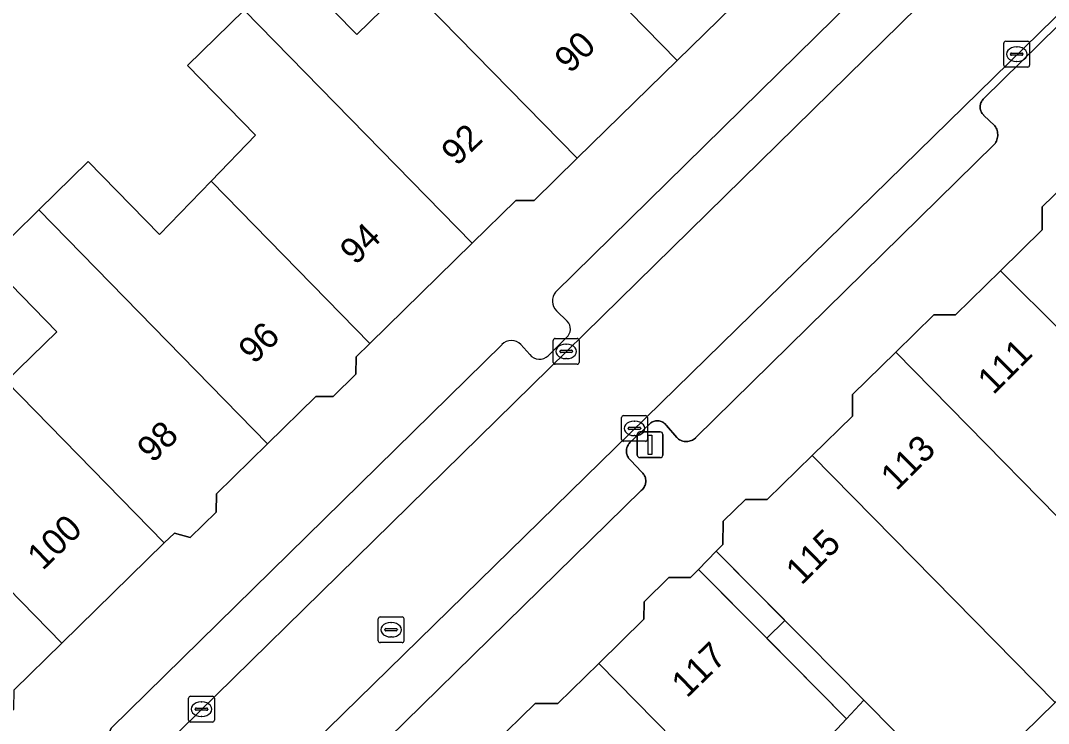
# Model space of a CAD drawing. Extents: x 160856 to 161310, y 384024 to 384878.
# Drawn here: x 161043.45 to 161083.27, y 384645.25 to 384672.48 of the extents above; entities that cross this region are included whole.
import ezdxf

# ---------------------------------------------------------------- set-up
doc = ezdxf.new("R2010")
doc.units = 0
for name, color, linetype in [('IMGEO_Erf', 7, 'Continuous'), ('IMGEO_Kolk', 7, 'Continuous'), ('IMGEO_Lichtmast', 7, 'Continuous'), ('IMGEO_Pand', 7, 'Continuous'), ('IMGEO_Pand_nummerreeks', 7, 'Continuous'), ('IMGEO_Pand_overbouw', 7, 'Continuous'), ('IMGEO_Parkeervlak_open', 7, 'Continuous'), ('IMGEO_Rijbaan_lokaal_gesloten', 7, 'Continuous'), ('IMGEO_Rioolput', 7, 'Continuous'), ('IMGEO_Voetpad_open', 7, 'Continuous')]:
    doc.layers.add(name, color=color, linetype=linetype)

msp = doc.modelspace()

# ---------------------------------------------------------------- linework, layer by layer
at = {"layer": 'IMGEO_Erf'}
for points in [[(161053.863, 384674.603), (161056.476, 384671.933), (161058.443, 384673.858)], [(161042.888, 384658.505), (161044.847, 384660.422), (161042.148, 384663.181), (161044.154, 384665.144), (161046.067, 384667.016), (161048.834, 384664.187), (161050.828, 384666.256), (161052.547, 384668.039), (161049.91, 384670.735), (161052.106, 384672.884)], [(161083.528, 384646.059), (161079.815, 384642.413), (161076.117, 384646.148), (161075.44, 384645.431), (161073.602, 384643.447)]]:
    msp.add_lwpolyline(points, dxfattribs=at)
msp.add_lwpolyline([(161069.712, 384651.21), (161073.232, 384647.659), (161075.44, 384645.431), (161076.117, 384646.148), (161073.917, 384648.37), (161070.398, 384651.922)], close=True, dxfattribs=at)
at = {"layer": 'IMGEO_Kolk'}
for p, q in [((161081.539, 384670.751), (161081.539, 384671.603)), ((161081.614, 384671.677), (161082.466, 384671.677)), ((161082.027, 384671.457), (161082.052, 384671.457)), ((161082.54, 384671.603), (161082.54, 384670.751)), ((161081.798, 384671.171), (161081.798, 384671.183)), ((161082.236, 384671.134), (161081.838, 384671.134)), ((161081.841, 384671.22), (161082.239, 384671.22)), ((161082.282, 384671.183), (161082.282, 384671.171)), ((161082.466, 384670.677), (161081.614, 384670.677)), ((161082.05, 384670.897), (161082.025, 384670.897)), ((161064.086, 384659.235), (161064.086, 384660.087)), ((161064.161, 384660.161), (161065.013, 384660.161)), ((161064.574, 384659.941), (161064.599, 384659.941)), ((161065.087, 384660.087), (161065.087, 384659.235)), ((161064.345, 384659.655), (161064.345, 384659.667)), ((161064.783, 384659.618), (161064.385, 384659.618)), ((161064.388, 384659.704), (161064.786, 384659.704)), ((161064.829, 384659.667), (161064.829, 384659.655)), ((161065.013, 384659.161), (161064.161, 384659.161)), ((161064.597, 384659.381), (161064.572, 384659.381)), ((161066.729, 384656.251), (161066.729, 384657.103)), ((161066.804, 384657.177), (161067.656, 384657.177)), ((161067.73, 384657.103), (161067.73, 384656.251)), ((161067.031, 384656.72), (161067.429, 384656.72)), ((161067.217, 384656.957), (161067.242, 384656.957)), ((161066.988, 384656.671), (161066.988, 384656.683)), ((161067.426, 384656.634), (161067.028, 384656.634)), ((161067.24, 384656.397), (161067.215, 384656.397)), ((161067.472, 384656.683), (161067.472, 384656.671)), ((161067.656, 384656.177), (161066.804, 384656.177)), ((161049.955, 384645.374), (161049.955, 384646.226)), ((161050.03, 384646.3), (161050.882, 384646.3)), ((161050.443, 384646.08), (161050.468, 384646.08)), ((161050.956, 384646.226), (161050.956, 384645.374)), ((161050.214, 384645.794), (161050.214, 384645.806)), ((161050.652, 384645.757), (161050.254, 384645.757)), ((161050.257, 384645.843), (161050.655, 384645.843)), ((161050.698, 384645.806), (161050.698, 384645.794)), ((161050.882, 384645.3), (161050.03, 384645.3)), ((161050.466, 384645.52), (161050.441, 384645.52))]:
    msp.add_line(p, q, dxfattribs=at)
for points in [[(161081.539, 384670.751), (161081.539, 384671.603)], [(161081.614, 384671.677), (161082.466, 384671.677)], [(161082.54, 384671.603), (161082.54, 384670.751)], [(161082.466, 384670.677), (161081.614, 384670.677)], [(161064.086, 384659.235), (161064.086, 384660.087)], [(161064.161, 384660.161), (161065.013, 384660.161)], [(161065.087, 384660.087), (161065.087, 384659.235)], [(161065.013, 384659.161), (161064.161, 384659.161)], [(161066.729, 384656.251), (161066.729, 384657.103)], [(161066.804, 384657.177), (161067.656, 384657.177)], [(161067.73, 384657.103), (161067.73, 384656.251)], [(161067.656, 384656.177), (161066.804, 384656.177)], [(161049.955, 384645.374), (161049.955, 384646.226)], [(161050.03, 384646.3), (161050.882, 384646.3)], [(161050.956, 384646.226), (161050.956, 384645.374)], [(161050.882, 384645.3), (161050.03, 384645.3)]]:
    msp.add_lwpolyline(points, dxfattribs=at)
for centre, radius, start, end in [((161081.616, 384671.601), 0.0765, 91.552, 178.448), ((161081.616, 384671.601), 0.0765, 91.552, 178.448), ((161082.464, 384671.601), 0.0765, 1.552, 88.448), ((161082.464, 384671.601), 0.0765, 1.552, 88.448), ((161081.838, 384671.18), 0.0403, 85.8775, 175.7526), ((161081.835, 384671.17), 0.0366, 178.938, 274.7102), ((161082.239, 384671.177), 0.043, 264.8664, 352.4533), ((161082.243, 384671.182), 0.0386, 1.7309, 96.639), ((161081.616, 384670.753), 0.0765, 181.552, 268.448), ((161081.616, 384670.753), 0.0765, 181.552, 268.448), ((161082.464, 384670.753), 0.0765, 271.552, 358.448), ((161082.464, 384670.753), 0.0765, 271.552, 358.448), ((161064.163, 384660.085), 0.0765, 91.552, 178.448), ((161064.163, 384660.085), 0.0765, 91.552, 178.448), ((161065.011, 384660.085), 0.0765, 1.552, 88.448), ((161065.011, 384660.085), 0.0765, 1.552, 88.448), ((161064.385, 384659.664), 0.0403, 85.8775, 175.7526), ((161064.382, 384659.654), 0.0366, 178.938, 274.7102), ((161064.786, 384659.661), 0.043, 264.8664, 352.4533), ((161064.79, 384659.666), 0.0386, 1.7309, 96.639), ((161064.163, 384659.237), 0.0765, 181.552, 268.448), ((161064.163, 384659.237), 0.0765, 181.552, 268.448), ((161065.011, 384659.237), 0.0765, 271.552, 358.448), ((161065.011, 384659.237), 0.0765, 271.552, 358.448), ((161066.806, 384657.101), 0.0765, 91.552, 178.448), ((161066.806, 384657.101), 0.0765, 91.552, 178.448), ((161067.654, 384657.101), 0.0765, 1.552, 88.448), ((161067.654, 384657.101), 0.0765, 1.552, 88.448), ((161067.028, 384656.68), 0.0403, 85.8775, 175.7526), ((161067.433, 384656.682), 0.0386, 1.7309, 96.639), ((161067.025, 384656.67), 0.0366, 178.938, 274.7102), ((161067.429, 384656.677), 0.043, 264.8664, 352.4533), ((161066.806, 384656.253), 0.0765, 181.552, 268.448), ((161066.806, 384656.253), 0.0765, 181.552, 268.448), ((161067.654, 384656.253), 0.0765, 271.552, 358.448), ((161067.654, 384656.253), 0.0765, 271.552, 358.448), ((161050.032, 384646.224), 0.0765, 91.552, 178.448), ((161050.032, 384646.224), 0.0765, 91.552, 178.448), ((161050.88, 384646.224), 0.0765, 1.552, 88.448), ((161050.88, 384646.224), 0.0765, 1.552, 88.448), ((161050.254, 384645.803), 0.0403, 85.8775, 175.7526), ((161050.251, 384645.793), 0.0366, 178.938, 274.7102), ((161050.655, 384645.8), 0.043, 264.8664, 352.4533), ((161050.659, 384645.805), 0.0386, 1.7309, 96.639), ((161050.032, 384645.376), 0.0765, 181.552, 268.448), ((161050.032, 384645.376), 0.0765, 181.552, 268.448), ((161050.88, 384645.376), 0.0765, 271.552, 358.448), ((161050.88, 384645.376), 0.0765, 271.552, 358.448)]:
    msp.add_arc(centre, radius, start, end, dxfattribs=at)
for centre, major_axis, ratio, start_param, end_param in [((161082.026, 384671.177), (-0.387, 0.002), 0.722429, 4.712389, 7.853982), ((161082.051, 384671.177), (-0.39, 0.002), 0.717154, 1.570796, 4.712389), ((161064.573, 384659.661), (-0.387, 0.002), 0.722429, 4.712389, 7.853982), ((161064.598, 384659.661), (-0.39, 0.002), 0.717154, 1.570796, 4.712389), ((161067.216, 384656.677), (-0.387, 0.002), 0.722429, 4.712389, 7.853982), ((161067.241, 384656.677), (-0.39, 0.002), 0.717154, 1.570796, 4.712389), ((161050.442, 384645.8), (-0.387, 0.002), 0.722429, 4.712389, 7.853982), ((161050.467, 384645.8), (-0.39, 0.002), 0.717154, 1.570796, 4.712389)]:
    msp.add_ellipse(centre, major_axis=major_axis, ratio=ratio, start_param=start_param, end_param=end_param, dxfattribs=at)
at = {"layer": 'IMGEO_Lichtmast'}
for p, q in [((161067.339, 384655.646), (161067.339, 384656.446)), ((161067.339, 384656.446), (161067.339, 384655.646)), ((161067.439, 384656.546), (161068.229, 384656.546)), ((161068.229, 384656.546), (161067.439, 384656.546)), ((161068.329, 384656.446), (161068.329, 384655.646)), ((161068.329, 384655.646), (161068.329, 384656.446)), ((161068.229, 384655.546), (161067.439, 384655.546)), ((161067.439, 384655.546), (161068.229, 384655.546))]:
    msp.add_line(p, q, dxfattribs=at)
msp.add_lwpolyline([(161067.759, 384656.421), (161067.909, 384656.421), (161067.909, 384655.671), (161067.759, 384655.671), (161067.759, 384656.421)], dxfattribs=at)
for centre, start, end in [((161067.439, 384656.446), 90, 180), ((161067.439, 384656.446), 90, 180), ((161068.229, 384656.446), 0, 90), ((161068.229, 384656.446), 360, 90), ((161067.439, 384655.646), 180, 270), ((161067.439, 384655.646), 180, 270), ((161068.229, 384655.646), 270, 0), ((161068.229, 384655.646), 270, 0)]:
    msp.add_arc(centre, 0.1, start, end, dxfattribs=at)
at = {"layer": 'IMGEO_Pand'}
for points in [[(161066.889, 384681.575), (161064.573, 384679.31), (161061.029, 384682.932), (161060.87, 384682.777), (161059.041, 384680.994), (161068.886, 384670.932), (161073.184, 384675.14)], [(161059.041, 384680.994), (161056.988, 384678.993), (161057.966, 384677.993), (161058.14, 384677.815), (161060.501, 384675.402), (161059.015, 384673.948), (161058.78, 384674.188), (161058.443, 384673.858), (161065.015, 384667.142), (161068.886, 384670.932)], [(161052.106, 384672.884), (161060.941, 384663.854), (161062.633, 384665.51), (161063.339, 384665.502), (161065.015, 384667.142), (161058.443, 384673.858), (161056.476, 384671.933), (161053.863, 384674.603)], [(161052.106, 384672.884), (161049.91, 384670.735), (161052.547, 384668.039), (161050.828, 384666.256), (161056.976, 384659.973), (161060.941, 384663.854)], [(161053.017, 384656.086), (161054.888, 384657.917), (161055.553, 384657.91), (161056.437, 384658.775), (161056.444, 384659.452), (161056.976, 384659.973), (161050.828, 384666.256), (161048.834, 384664.187), (161046.067, 384667.016), (161044.154, 384665.144)], [(161081.413, 384662.783), (161091.066, 384653.171), (161092.786, 384654.859), (161088.969, 384658.818), (161090.858, 384660.647), (161088.603, 384662.951), (161085.106, 384666.524), (161084.662, 384666.101), (161083.9, 384666.108), (161083.032, 384665.256), (161083.024, 384664.365)], [(161042.888, 384658.505), (161040.875, 384656.536), (161038.16, 384659.312), (161037.93, 384659.087), (161034.44, 384662.655), (161035.691, 384663.879), (161033.998, 384665.608), (161033.779, 384665.832), (161030.805, 384662.922), (161032.749, 384660.935), (161036.163, 384657.446), (161045.05, 384648.363), (161049.014, 384652.243)], [(161042.888, 384658.505), (161049.014, 384652.243), (161049.404, 384652.625), (161050.019, 384652.453), (161051.025, 384653.438), (161051.032, 384654.143), (161053.017, 384656.086), (161044.154, 384665.144), (161042.148, 384663.181), (161044.847, 384660.422)], [(161081.413, 384662.783), (161079.67, 384661.072), (161078.831, 384661.079), (161077.352, 384659.628), (161086.407, 384650.417), (161088.242, 384652.221), (161090.2, 384650.207), (161092.135, 384652.106), (161091.066, 384653.171)], [(161074.12, 384655.63), (161083.528, 384646.059), (161085.285, 384647.785), (161084.521, 384648.564), (161086.407, 384650.417), (161077.352, 384659.628), (161075.683, 384657.989), (161075.675, 384657.157)], [(161036.163, 384657.446), (161035.583, 384656.879), (161034.191, 384655.517), (161032.2, 384653.569), (161032.68, 384653.079), (161032.814, 384652.942), (161041.458, 384644.107), (161043.184, 384645.796), (161043.192, 384646.544), (161045.05, 384648.363)], [(161074.12, 384655.63), (161072.375, 384653.917), (161071.527, 384653.925), (161070.668, 384653.081), (161070.66, 384652.18), (161070.398, 384651.922), (161073.917, 384648.37), (161076.117, 384646.148), (161079.815, 384642.413), (161083.528, 384646.059)], [(161073.232, 384647.659), (161069.712, 384651.21), (161069.403, 384650.896), (161068.562, 384650.904), (161067.6, 384649.959), (161067.594, 384649.283), (161065.854, 384647.575), (161075.279, 384637.98), (161077.157, 384639.826), (161073.602, 384643.447), (161075.44, 384645.431)], [(161065.854, 384647.575), (161064.267, 384646.017), (161063.379, 384646.026), (161061.742, 384644.419), (161068.073, 384637.979), (161069.834, 384639.708), (161073.371, 384636.105), (161074.297, 384637.015), (161075.279, 384637.98)]]:
    msp.add_lwpolyline(points, close=True, dxfattribs=at)
at = {"layer": 'IMGEO_Pand_overbouw'}
for points in [[(161072.352, 384648.547), (161073.053, 384649.242), (161070.398, 384651.922), (161069.712, 384651.21)], [(161073.917, 384648.37), (161073.053, 384649.242), (161072.352, 384648.547), (161075.44, 384645.431), (161076.117, 384646.148)]]:
    msp.add_lwpolyline(points, close=True, dxfattribs=at)
at = {"layer": 'IMGEO_Parkeervlak_open'}
for points in [[(161045.943, 384641.353), (161047.62, 384642.996), (161093.847, 384688.359), (161094.179, 384688.665), (161098.356, 384692.696)], [(161096.984, 384685.767), (161048.906, 384638.739)], [(161075.693, 384673.266), (161064.172, 384661.961)], [(161052.469, 384639.551), (161067.493, 384654.272), (161067.525, 384654.299), (161067.554, 384654.33), (161067.58, 384654.362), (161067.603, 384654.397), (161067.623, 384654.434), (161067.64, 384654.473), (161067.653, 384654.512), (161067.662, 384654.553), (161067.668, 384654.595), (161067.67, 384654.636), (161067.668, 384654.678), (161067.663, 384654.72), (161067.654, 384654.761), (161067.641, 384654.801), (161067.625, 384654.839), (161067.605, 384654.876), (161067.583, 384654.911), (161067.557, 384654.944), (161067.528, 384654.975), (161067.507, 384654.994), (161067.089, 384655.439), (161067.058, 384655.466), (161067.029, 384655.496), (161067.004, 384655.528), (161066.981, 384655.563), (161066.962, 384655.599), (161066.946, 384655.636), (161066.933, 384655.675), (161066.924, 384655.715), (161066.918, 384655.756), (161066.916, 384655.797), (161066.918, 384655.838), (161066.924, 384655.879), (161066.933, 384655.919), (161066.945, 384655.958), (161066.961, 384655.996), (161066.981, 384656.032), (161067.003, 384656.066), (161067.029, 384656.098), (161067.057, 384656.128), (161067.787, 384656.813), (161067.839, 384656.868), (161067.868, 384656.892), (161067.899, 384656.913), (161067.933, 384656.932), (161067.967, 384656.947), (161068.003, 384656.959), (161068.04, 384656.968), (161068.077, 384656.973), (161068.115, 384656.975), (161068.153, 384656.974), (161068.191, 384656.969), (161068.228, 384656.961), (161068.264, 384656.95), (161068.299, 384656.936), (161068.332, 384656.918), (161068.364, 384656.898), (161068.394, 384656.874), (161068.422, 384656.849), (161068.447, 384656.82), (161068.47, 384656.79), (161068.866, 384656.326), (161068.901, 384656.294), (161068.938, 384656.265), (161068.978, 384656.24), (161069.02, 384656.218), (161069.064, 384656.2), (161069.109, 384656.186), (161069.155, 384656.176), (161069.202, 384656.17), (161069.249, 384656.169), (161069.297, 384656.172), (161069.343, 384656.179), (161069.389, 384656.19), (161069.434, 384656.205), (161069.477, 384656.224), (161069.519, 384656.247), (161069.558, 384656.274), (161069.594, 384656.304), (161069.612, 384656.32), (161081.171, 384667.678), (161081.202, 384667.72), (161081.23, 384667.764), (161081.253, 384667.81), (161081.273, 384667.858), (161081.288, 384667.908), (161081.298, 384667.959), (161081.304, 384668.011), (161081.305, 384668.063), (161081.301, 384668.115), (161081.293, 384668.166), (161081.28, 384668.217), (161081.263, 384668.266), (161081.242, 384668.313), (161081.216, 384668.359), (161081.187, 384668.402), (161081.176, 384668.415), (161080.769, 384668.806), (161080.752, 384668.822), (161080.726, 384668.851), (161080.702, 384668.882), (161080.68, 384668.915), (161080.662, 384668.951), (161080.647, 384668.987), (161080.636, 384669.025), (161080.628, 384669.064), (161080.623, 384669.103), (161080.622, 384669.143), (161080.624, 384669.182), (161080.63, 384669.221), (161080.64, 384669.26), (161080.653, 384669.297), (161080.669, 384669.333), (161080.688, 384669.368), (161080.71, 384669.4), (161080.735, 384669.431), (161080.763, 384669.459), (161083.642, 384672.284)], [(161064.208, 384661.229), (161064.625, 384660.828)], [(161062.098, 384659.927), (161046.962, 384645.066), (161046.654, 384644.358), (161046.58, 384642.692)], [(161063.175, 384659.539), (161062.823, 384659.924)], [(161064.593, 384660.198), (161063.883, 384659.493)]]:
    msp.add_lwpolyline(points, dxfattribs=at)
for centre, radius, start, end in [((161064.606, 384661.615), 0.555, 141.4949, 224.1363), ((161064.322, 384660.528), 0.427, 309.4723, 44.7122), ((161062.459, 384659.599), 0.488, 41.7355, 137.7903), ((161063.55, 384659.84), 0.481, 218.7209, 313.8443)]:
    msp.add_arc(centre, radius, start, end, dxfattribs=at)
at = {"layer": 'IMGEO_Rijbaan_lokaal_gesloten'}
msp.add_lwpolyline([(161045.97, 384635.823), (161048.906, 384638.739), (161096.984, 384685.767), (161094.179, 384688.665), (161093.847, 384688.359), (161047.62, 384642.996), (161045.943, 384641.353), (161041.622, 384637.072), (161035.757, 384631.338), (161021.935, 384619.355), (161000, 384600.273), (160978.384, 384581.429), (160977.321, 384580.465), (160976.957, 384580.135), (160976.745, 384579.943)], dxfattribs=at)
at = {"layer": 'IMGEO_Rioolput'}
for p, q in [((161057.3, 384648.451), (161057.3, 384649.303)), ((161057.375, 384649.377), (161058.227, 384649.377)), ((161057.788, 384649.157), (161057.813, 384649.157)), ((161058.301, 384649.303), (161058.301, 384648.451)), ((161057.559, 384648.871), (161057.559, 384648.883)), ((161057.997, 384648.834), (161057.599, 384648.834)), ((161057.602, 384648.92), (161058, 384648.92)), ((161058.043, 384648.883), (161058.043, 384648.871)), ((161058.227, 384648.377), (161057.375, 384648.377)), ((161057.811, 384648.597), (161057.786, 384648.597))]:
    msp.add_line(p, q, dxfattribs=at)
for points in [[(161057.3, 384648.451), (161057.3, 384649.303)], [(161057.375, 384649.377), (161058.227, 384649.377)], [(161058.301, 384649.303), (161058.301, 384648.451)], [(161058.227, 384648.377), (161057.375, 384648.377)]]:
    msp.add_lwpolyline(points, dxfattribs=at)
for centre, radius, start, end in [((161057.377, 384649.301), 0.0765, 91.552, 178.448), ((161057.377, 384649.301), 0.0765, 91.552, 178.448), ((161058.225, 384649.301), 0.0765, 1.552, 88.448), ((161058.225, 384649.301), 0.0765, 1.552, 88.448), ((161057.599, 384648.88), 0.0403, 85.8775, 175.7526), ((161057.596, 384648.87), 0.0366, 178.938, 274.7102), ((161058, 384648.877), 0.043, 264.8664, 352.4533), ((161058.004, 384648.882), 0.0386, 1.7309, 96.639), ((161057.377, 384648.453), 0.0765, 181.552, 268.448), ((161057.377, 384648.453), 0.0765, 181.552, 268.448), ((161058.225, 384648.453), 0.0765, 271.552, 358.448), ((161058.225, 384648.453), 0.0765, 271.552, 358.448)]:
    msp.add_arc(centre, radius, start, end, dxfattribs=at)
for centre, major_axis, ratio, start_param, end_param in [((161057.787, 384648.877), (-0.387, 0.002), 0.722429, 4.712389, 7.853982), ((161057.812, 384648.877), (-0.39, 0.002), 0.717154, 1.570796, 4.712389)]:
    msp.add_ellipse(centre, major_axis=major_axis, ratio=ratio, start_param=start_param, end_param=end_param, dxfattribs=at)
at = {"layer": 'IMGEO_Voetpad_open'}
for points in [[(161089.608, 384691.356), (161082.942, 384684.859), (161081.588, 384683.366), (161077.149, 384679.021), (161073.184, 384675.14), (161068.886, 384670.932), (161065.015, 384667.142), (161063.339, 384665.502), (161062.633, 384665.51), (161060.941, 384663.854), (161056.976, 384659.973), (161056.444, 384659.452), (161056.437, 384658.775), (161055.553, 384657.91), (161054.888, 384657.917), (161053.017, 384656.086), (161051.032, 384654.143), (161051.025, 384653.438), (161050.019, 384652.453), (161049.404, 384652.625), (161049.014, 384652.243), (161045.05, 384648.363), (161043.192, 384646.544)], [(161064.172, 384661.961), (161075.693, 384673.266)], [(161083.642, 384672.284), (161080.763, 384669.459), (161080.735, 384669.431), (161080.71, 384669.4), (161080.688, 384669.368), (161080.669, 384669.333), (161080.653, 384669.297), (161080.64, 384669.26), (161080.63, 384669.221), (161080.624, 384669.182), (161080.622, 384669.143), (161080.623, 384669.103), (161080.628, 384669.064), (161080.636, 384669.025), (161080.647, 384668.987), (161080.662, 384668.951), (161080.68, 384668.915), (161080.702, 384668.882), (161080.726, 384668.851), (161080.752, 384668.822), (161080.769, 384668.806), (161081.176, 384668.415), (161081.187, 384668.402), (161081.216, 384668.359), (161081.242, 384668.313), (161081.263, 384668.266), (161081.28, 384668.217), (161081.293, 384668.166), (161081.301, 384668.115), (161081.305, 384668.063), (161081.304, 384668.011), (161081.298, 384667.959), (161081.288, 384667.908), (161081.273, 384667.858), (161081.253, 384667.81), (161081.23, 384667.764), (161081.202, 384667.72), (161081.171, 384667.678), (161069.612, 384656.32), (161069.594, 384656.304), (161069.558, 384656.274), (161069.519, 384656.247), (161069.477, 384656.224), (161069.434, 384656.205), (161069.389, 384656.19), (161069.343, 384656.179), (161069.297, 384656.172), (161069.249, 384656.169), (161069.202, 384656.17), (161069.155, 384656.176), (161069.109, 384656.186), (161069.064, 384656.2), (161069.02, 384656.218), (161068.978, 384656.24), (161068.938, 384656.265), (161068.901, 384656.294), (161068.866, 384656.326), (161068.47, 384656.79), (161068.447, 384656.82), (161068.422, 384656.849), (161068.394, 384656.874), (161068.364, 384656.898), (161068.332, 384656.918), (161068.299, 384656.936), (161068.264, 384656.95), (161068.228, 384656.961), (161068.191, 384656.969), (161068.153, 384656.974), (161068.115, 384656.975), (161068.077, 384656.973), (161068.04, 384656.968), (161068.003, 384656.959), (161067.967, 384656.947), (161067.933, 384656.932), (161067.899, 384656.913), (161067.868, 384656.892), (161067.839, 384656.868), (161067.787, 384656.813), (161067.057, 384656.128), (161067.029, 384656.098), (161067.003, 384656.066), (161066.981, 384656.032), (161066.961, 384655.996), (161066.945, 384655.958), (161066.933, 384655.919), (161066.924, 384655.879), (161066.918, 384655.838), (161066.916, 384655.797), (161066.918, 384655.756), (161066.924, 384655.715), (161066.933, 384655.675), (161066.946, 384655.636), (161066.962, 384655.599), (161066.981, 384655.563), (161067.004, 384655.528), (161067.029, 384655.496), (161067.058, 384655.466), (161067.089, 384655.439), (161067.507, 384654.994), (161067.528, 384654.975), (161067.557, 384654.944), (161067.583, 384654.911), (161067.605, 384654.876), (161067.625, 384654.839), (161067.641, 384654.801), (161067.654, 384654.761), (161067.663, 384654.72), (161067.668, 384654.678), (161067.67, 384654.636), (161067.668, 384654.595), (161067.662, 384654.553), (161067.653, 384654.512), (161067.64, 384654.473), (161067.623, 384654.434), (161067.603, 384654.397), (161067.58, 384654.362), (161067.554, 384654.33), (161067.525, 384654.299), (161067.493, 384654.272), (161052.469, 384639.551)], [(161061.742, 384644.419), (161063.379, 384646.026), (161064.267, 384646.017), (161065.854, 384647.575), (161067.594, 384649.283), (161067.6, 384649.959), (161068.562, 384650.904), (161069.403, 384650.896), (161069.712, 384651.21), (161070.398, 384651.922), (161070.66, 384652.18), (161070.668, 384653.081), (161071.527, 384653.925), (161072.375, 384653.917), (161074.12, 384655.63), (161075.675, 384657.157), (161075.683, 384657.989), (161077.352, 384659.628), (161078.831, 384661.079), (161079.67, 384661.072), (161081.413, 384662.783), (161083.024, 384664.365), (161083.032, 384665.256), (161083.9, 384666.108)], [(161064.625, 384660.828), (161064.208, 384661.229)], [(161046.58, 384642.692), (161046.654, 384644.358), (161046.962, 384645.066), (161062.098, 384659.927)], [(161062.823, 384659.924), (161063.175, 384659.539)], [(161063.883, 384659.493), (161064.593, 384660.198)]]:
    msp.add_lwpolyline(points, dxfattribs=at)
for centre, radius, start, end in [((161064.606, 384661.615), 0.555, 141.4949, 224.1363), ((161064.322, 384660.528), 0.427, 309.4723, 44.7122), ((161062.459, 384659.599), 0.488, 41.7355, 137.7903), ((161063.55, 384659.84), 0.481, 218.7209, 313.8443)]:
    msp.add_arc(centre, radius, start, end, dxfattribs=at)

# ---------------------------------------------------------------- texts
at = {"layer": 'IMGEO_Pand_nummerreeks'}
for s, rotation, p in [('90', 44.387, (161064.735, 384670.395)), ('92', 44.3085, (161060.347, 384666.805)), ('94', 44.3085, (161056.419, 384662.971)), ('96', 44.3085, (161052.49, 384659.135)), ('111', 44.7928, (161081.133, 384657.957)), ('98', 44.3085, (161048.562, 384655.302)), ('113', 44.7928, (161077.376, 384654.228)), ('100', 44.3068, (161044.304, 384651.146)), ('115', 44.7928, (161073.699, 384650.577)), ('117', 44.1006, (161069.26, 384646.206))]:
    msp.add_text(s, height=1, rotation=rotation, dxfattribs=at).set_placement(p)

doc.saveas('drawing.dxf')
